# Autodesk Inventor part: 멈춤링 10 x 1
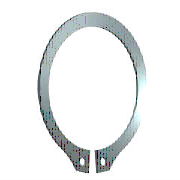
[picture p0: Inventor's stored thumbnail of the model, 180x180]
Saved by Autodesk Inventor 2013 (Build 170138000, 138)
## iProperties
IsCustomPart: 0
Company: 한국ATC센터
Created: 2014-07
Part Number: 멈춤링 10 x 1
Material: Steel, Mild
Description: 리테이닝 링(C형)
Document SubType Name: Modeling
Standard: KS B 1336
Designer: KYOUNG IL JANG
Standards Organization: KS
Language: ko-KR
Size Designation: 10 x 1
Categories: <MemberInstance><Categories><Category DisplayName="샤프트 부품" InternalName="7f7aeb1f-a693-4053-b835-cee3144e0d98" Mnemonic="SHFT"><Category DisplayName="써클립" Inter
Density: 1 g/cm^3
Author: KYOUNG IL JANG
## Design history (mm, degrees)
sketch "스케치1"
  geometry: L1 (-6, 0)-(6, 0) reference; L2 (0, 20.189)-(0, -80.536) reference; L3 (-48.09, 0)-(48.09, 0) reference; L4 (-0.3, -9.791)-(-0.3, -12.791); L5 (-0.3, -6.54)-(-0.3, -13.29); L6 (-2.795, 1.6)-(3.672, 1.6); L7 (0.3, -6.54)-(0.3, -13.29); L8 (0.3, -9.791)-(0.3, -12.791); C1 r 0.6 at (-1.2, -11.486); C2 r 0.6 at (1.2, -11.486); A1 r 4.8 centre (0, -5) between (0.3, -9.791) and (-0.3, -9.791); A2 r 6.2 centre (0, -4.6) between (2.988, -10.033) and (-2.988, -10.033); A3 r 7.796 centre (0, -5) between (-1.418, -12.666) and (-0.3, -12.791); A4 r 1.2 centre (-1.2, -11.486) between (-2.383, -11.285) and (-1.418, -12.666); A5 r 1.2 centre (-3.566, -11.084) between (-2.383, -11.285) and (-2.988, -10.033); A6 r 1.2 centre (3.566, -11.084) between (2.988, -10.033) and (2.383, -11.285); A7 r 1.2 centre (1.2, -11.486) between (1.418, -12.666) and (2.383, -11.285); A8 r 7.796 centre (0, -5) between (0.3, -12.791) and (1.418, -12.666)
  constraints: 16 point on circle, 12 end point, 10 centre point, 9 symmetric about line, 5 point on line, 4 tangent, 3 coincident, 2 horizontal, 1 perpendicular, 1 vertical, 5 other
  dimensions: "d0" = 9.6 diameter of A1 (= ND); "d1" = 3 distance of L4.end L4.start (= SRB2); "d6" = 0.3 distance between parallel lines of L2 L5 (= 0.25 x SD5); "d7" = 1.6 distance between parallel lines of L6 L3 (= SRB1); "d8" = 0.4 distance of A1.centre A2.centre (= 0.25 x SRB1); "d9" = 1.2 radius of A4 (= SD5); "d10" = 1.2 radius of A5 (= SD5); "d11" = 0.9 distance from line of L4 A4.centre (= 0.75 x SD5); "d12" = 1.2 diameter of C1 (= SD5); "d13" = 1.2 diameter of C2 (= SD5); "d14" = 5 distance from line of A1.centre L1 (= 0.5 x WD)
extrude "본체" new body sketch "스케치1" distance "d2" = 1 (= SD); taper "d3" = 0 deg
workaxis "Work Axis1"
workplane "Work Plane1"
body "Solid1"
other parameters: "SD" = 1 [user parameter; used in 1 equation term], "SRB1" = 1.6 [user parameter; used in 2 equation terms], "ND" = 9.6 [user parameter; used in 1 equation term], "SRB2" = 3 [user parameter; used in 1 equation term], "SD5" = 1.2 [user parameter; used in 6 equation terms], "d15" = 0, "d16" = 0, "d17" = 0, "d41" = 0, "d42" = 0, "SD3" = 9.3 [user parameter], "WDMAX" = 11 [user parameter]
